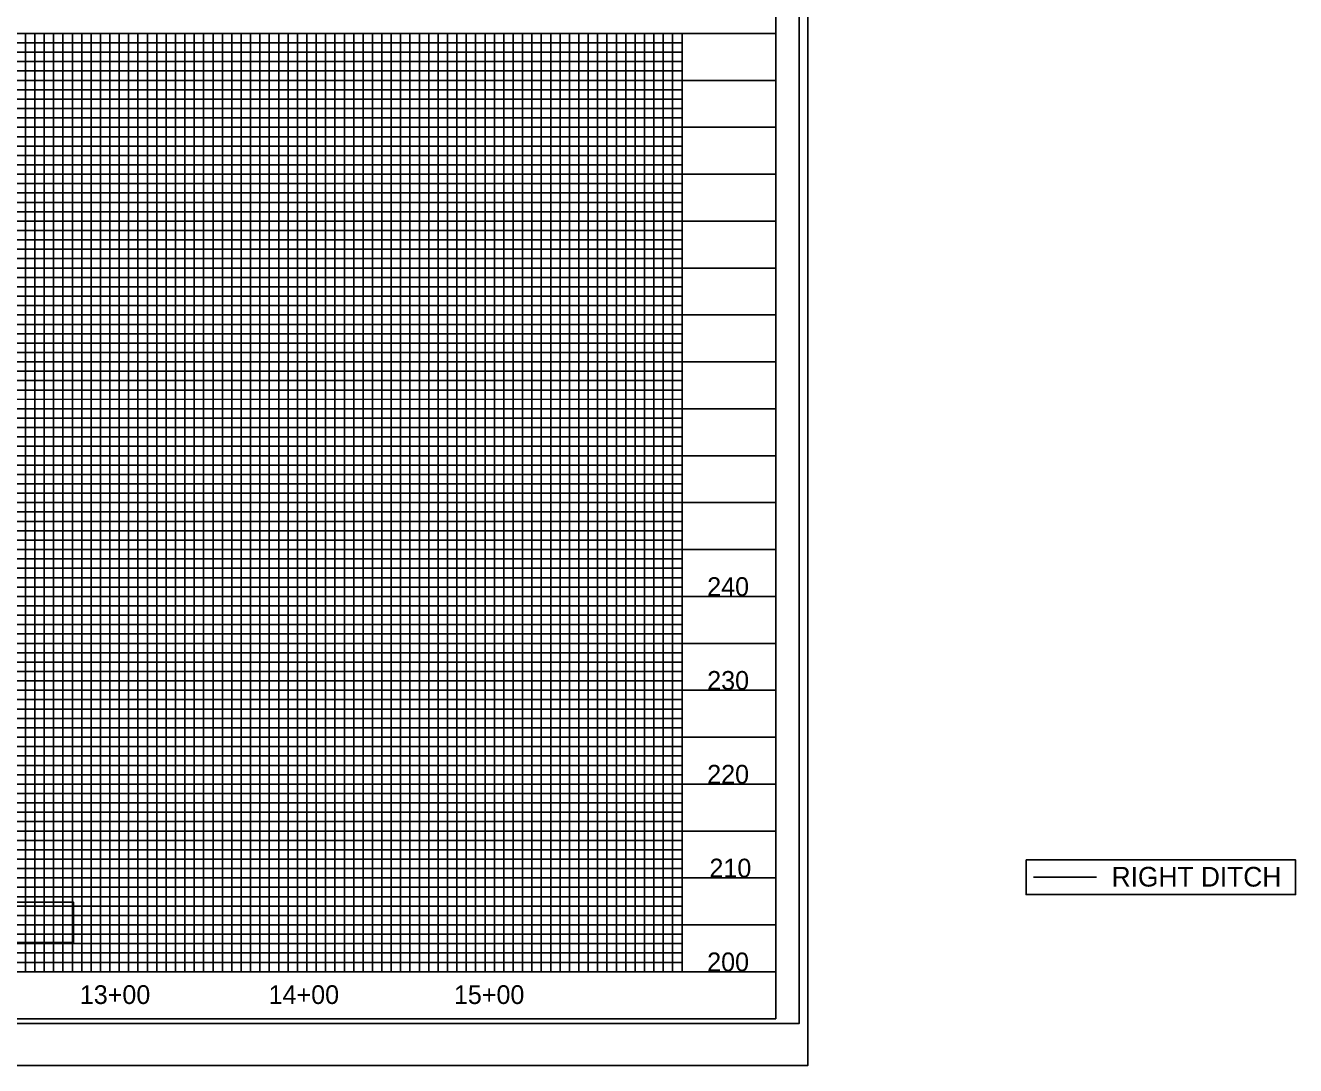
# Model space of a CAD drawing. Extents: x 1810963 to 1812908, y 722070 to 723170.
# Drawn here: x 1812230 to 1812908, y 722070 to 722624 of the extents above; entities that cross this region are included whole.
import ezdxf

# ---------------------------------------------------------------- set-up
doc = ezdxf.new("R2010")
doc.units = 0
for name, color, linetype in [('Exist Horizontal Alignment Tick Label', 7, 'Continuous'), ('Old_Level_11', 7, 'Continuous'), ('Old_Level_2', 7, 'Continuous'), ('Prop Conc 2ft 6in Curb and Gutter', 7, 'Continuous'), ('Prop PFL VPI Symbol CELL', 7, 'Continuous'), ('Prop RDY Traffic Signal CELL', 7, 'Continuous'), ('Prop Shade Heavy', 7, 'Continuous'), ('Prop Shade Light', 7, 'Continuous'), ('Prop Vertical Profile Ditch Grade Right', 7, 'Continuous'), ('Scratch_Level_0', 7, 'Continuous'), ('Sheet Block Title CELL', 7, 'Continuous'), ('Sheet North Arrow CELL', 7, 'Continuous'), ('Sheet Symbology CELL', 7, 'Continuous'), ('Sheet Title CELL', 7, 'Continuous')]:
    doc.layers.add(name, color=color, linetype=linetype)

msp = doc.modelspace()

# ---------------------------------------------------------------- linework, layer by layer
at = {"layer": 'Old_Level_11'}
msp.add_lwpolyline([(1810976.46, 722092.33), (1812642.96, 722092.33), (1812642.96, 723147.43), (1810976.46, 723147.43)], close=True, dxfattribs=at)
at = {"layer": 'Old_Level_2'}
for points in [[(1812763.88, 722179.51), (1812907.55, 722179.51), (1812907.55, 722161.02), (1812763.88, 722161.02)], [(1811986.45, 722156.96), (1812256.15, 722156.96), (1812256.15, 722135.44), (1811986.45, 722135.44)]]:
    msp.add_lwpolyline(points, close=True, dxfattribs=at)
at = {"layer": 'Prop Conc 2ft 6in Curb and Gutter'}
for p, q in [((1811130.46, 722619.88), (1812630.35, 722619.88)), ((1812230.46, 722619.88), (1812230.46, 722119.88)), ((1812280.46, 722619.88), (1812280.46, 722119.88)), ((1812330.46, 722619.88), (1812330.46, 722119.88)), ((1812380.46, 722619.88), (1812380.46, 722119.88)), ((1812430.46, 722619.88), (1812430.46, 722119.88)), ((1812480.46, 722619.88), (1812480.46, 722119.88)), ((1812530.46, 722619.88), (1812530.46, 722119.88)), ((1812580.46, 722619.88), (1812580.46, 722119.88)), ((1811130.46, 722569.88), (1812630.35, 722569.88)), ((1811130.46, 722519.88), (1812630.35, 722519.88)), ((1811130.46, 722469.88), (1812630.35, 722469.88)), ((1811130.46, 722419.88), (1812630.35, 722419.88)), ((1811130.46, 722369.88), (1812630.35, 722369.88)), ((1811130.46, 722319.88), (1812630.35, 722319.88)), ((1811130.46, 722269.88), (1812630.35, 722269.88)), ((1811130.46, 722219.88), (1812630.35, 722219.88)), ((1811130.46, 722169.88), (1812630.35, 722169.88))]:
    msp.add_line(p, q, dxfattribs=at)
at = {"layer": 'Prop PFL VPI Symbol CELL'}
msp.add_lwpolyline([(1811180.46, 722619.88), (1812580.46, 722619.88), (1812580.46, 722119.88), (1811180.46, 722119.88)], close=True, dxfattribs=at)
at = {"layer": 'Prop RDY Traffic Signal CELL'}
msp.add_line((1810963.46, 722069.88), (1812647.46, 722069.88), dxfattribs=at)
at = {"layer": 'Prop Shade Heavy'}
for p, q in [((1812230.46, 722619.88), (1812280.46, 722619.88)), ((1812330.46, 722619.88), (1812380.46, 722619.88)), ((1812430.46, 722619.88), (1812480.46, 722619.88)), ((1812530.46, 722619.88), (1812580.46, 722619.88)), ((1812530.46, 722119.88), (1812530.46, 722119.88))]:
    msp.add_line(p, q, dxfattribs=at)
for points in [[(1812180.46, 722119.88), (1812230.46, 722119.88), (1812230.46, 722619.88), (1812280.46, 722619.88), (1812280.46, 722119.88), (1812330.46, 722119.88), (1812330.46, 722619.88), (1812380.46, 722619.88), (1812380.46, 722119.88), (1812430.46, 722119.88), (1812430.46, 722619.88), (1812480.46, 722619.88), (1812480.46, 722119.88), (1812530.46, 722119.88), (1812530.46, 722119.88), (1812530.46, 722619.88), (1812580.46, 722619.88), (1812580.46, 722119.88)], [(1812630.46, 722569.88), (1811130.46, 722569.88)], [(1812630.46, 722519.88), (1811130.46, 722519.88), (1811130.46, 722469.88), (1812630.46, 722469.88)], [(1812630.46, 722419.88), (1811130.46, 722419.88), (1811130.46, 722369.88), (1812630.46, 722369.88)], [(1812630.46, 722319.88), (1811130.46, 722319.88), (1811130.46, 722269.88), (1812630.46, 722269.88)], [(1812630.46, 722219.88), (1811130.46, 722219.88), (1811130.46, 722219.88), (1811130.46, 722169.88), (1812630.46, 722169.88)], [(1812630.46, 722119.88), (1811130.46, 722119.88)]]:
    msp.add_lwpolyline(points, dxfattribs=at)
at = {"layer": 'Prop Shade Light'}
for points in [[(1812205.46, 722119.88), (1812255.46, 722119.88), (1812255.46, 722619.88), (1812305.46, 722619.88), (1812305.46, 722119.88), (1812355.46, 722119.88), (1812355.46, 722619.88), (1812405.46, 722619.88), (1812405.46, 722119.88), (1812455.46, 722119.88), (1812455.46, 722619.88), (1812505.46, 722619.88), (1812505.46, 722119.88), (1812555.46, 722119.88), (1812555.46, 722619.88)], [(1811130.46, 722594.88), (1812630.46, 722594.88)], [(1812630.46, 722544.88), (1811130.46, 722544.88), (1811130.46, 722494.88), (1812630.46, 722494.88)], [(1812630.46, 722444.88), (1811130.46, 722444.88), (1811130.46, 722394.88), (1812630.46, 722394.88)], [(1812630.46, 722344.88), (1811130.46, 722344.88), (1811130.46, 722294.88), (1812630.46, 722294.88)], [(1812630.46, 722244.88), (1811130.46, 722244.88), (1811130.46, 722194.88), (1812630.46, 722194.88)], [(1812630.46, 722144.88), (1811130.46, 722144.88)]]:
    msp.add_lwpolyline(points, dxfattribs=at)
at = {"layer": 'Prop Vertical Profile Ditch Grade Right'}
msp.add_line((1812767.79, 722170.2), (1812801.44, 722170.2), dxfattribs=at)
at = {"layer": 'Sheet North Arrow CELL'}
msp.add_lwpolyline([(1810963.46, 722069.88), (1812647.46, 722069.88), (1812647.46, 723169.88), (1810963.46, 723169.88)], close=True, dxfattribs=at)
at = {"layer": 'Sheet Symbology CELL'}
for p, q in [((1811130.46, 722619.88), (1812630.46, 722619.88)), ((1812630.46, 722119.88), (1811130.46, 722119.88)), ((1811130.46, 722094.88), (1812630.46, 722094.88))]:
    msp.add_line(p, q, dxfattribs=at)
msp.add_lwpolyline([(1812630.46, 723144.88), (1811130.46, 723144.88), (1811130.46, 722094.88), (1812630.46, 722094.88)], close=True, dxfattribs=at)
at = {"layer": 'Sheet Title CELL'}
for p, q in [((1811180.46, 722614.88), (1812580.46, 722614.88)), ((1812580.46, 722609.88), (1811180.46, 722609.88)), ((1811180.46, 722604.88), (1812580.46, 722604.88)), ((1812580.46, 722599.88), (1811180.46, 722599.88)), ((1811180.46, 722589.88), (1812580.46, 722589.88)), ((1812580.46, 722584.88), (1811180.46, 722584.88)), ((1811180.46, 722579.88), (1812580.46, 722579.88)), ((1812580.46, 722574.88), (1811180.46, 722574.88)), ((1811180.46, 722564.88), (1812580.46, 722564.88)), ((1812580.46, 722559.88), (1811180.46, 722559.88)), ((1811180.46, 722554.88), (1812580.46, 722554.88)), ((1812580.46, 722549.88), (1811180.46, 722549.88)), ((1811180.46, 722539.88), (1812580.46, 722539.88)), ((1812580.46, 722534.88), (1811180.46, 722534.88)), ((1811180.46, 722529.88), (1812580.46, 722529.88)), ((1812580.46, 722524.88), (1811180.46, 722524.88)), ((1811180.46, 722514.88), (1812580.46, 722514.88)), ((1812580.46, 722509.88), (1811180.46, 722509.88)), ((1811180.46, 722504.88), (1812580.46, 722504.88)), ((1812580.46, 722499.88), (1811180.46, 722499.88)), ((1811180.46, 722489.88), (1812580.46, 722489.88)), ((1812580.46, 722484.88), (1811180.46, 722484.88)), ((1811180.46, 722479.88), (1812580.46, 722479.88)), ((1812580.46, 722474.88), (1811180.46, 722474.88)), ((1811180.46, 722464.88), (1812580.46, 722464.88)), ((1812580.46, 722459.88), (1811180.46, 722459.88)), ((1811180.46, 722454.88), (1812580.46, 722454.88)), ((1812580.46, 722449.88), (1811180.46, 722449.88)), ((1811180.46, 722439.88), (1812580.46, 722439.88)), ((1812580.46, 722434.88), (1811180.46, 722434.88)), ((1811180.46, 722429.88), (1812580.46, 722429.88)), ((1812580.46, 722424.88), (1811180.46, 722425.03)), ((1811180.46, 722414.88), (1812580.46, 722414.88)), ((1812580.46, 722409.88), (1811180.46, 722409.88)), ((1811180.46, 722404.88), (1812580.46, 722404.88)), ((1812580.46, 722399.88), (1811180.46, 722399.88)), ((1811180.46, 722389.88), (1812580.46, 722389.88)), ((1812580.46, 722384.88), (1811180.46, 722384.88)), ((1811180.46, 722379.88), (1812580.46, 722379.88)), ((1812580.46, 722374.88), (1811180.46, 722374.88)), ((1811180.46, 722364.88), (1812580.46, 722364.88)), ((1812580.46, 722359.88), (1811180.46, 722359.88)), ((1811180.46, 722354.88), (1812580.46, 722354.88)), ((1812580.46, 722349.88), (1811180.46, 722349.88)), ((1811180.46, 722339.88), (1812580.46, 722339.88)), ((1812580.46, 722334.88), (1811180.46, 722334.88)), ((1811180.46, 722329.88), (1812580.46, 722329.88)), ((1812580.46, 722324.88), (1811180.46, 722324.88)), ((1811180.46, 722314.88), (1812580.46, 722314.88)), ((1812580.46, 722309.88), (1811180.46, 722309.88)), ((1811180.46, 722304.88), (1812580.46, 722304.88)), ((1812580.46, 722299.88), (1811180.46, 722299.88)), ((1811180.46, 722289.88), (1812580.46, 722289.88)), ((1812580.46, 722284.88), (1811180.46, 722284.88)), ((1811180.46, 722279.88), (1812580.46, 722279.88)), ((1812580.46, 722274.88), (1811180.46, 722274.88)), ((1811180.46, 722264.88), (1812580.46, 722264.88)), ((1812580.46, 722259.88), (1811180.46, 722259.88)), ((1811180.46, 722254.88), (1812580.46, 722254.88)), ((1812580.46, 722249.88), (1811180.46, 722249.88)), ((1811180.46, 722239.88), (1812580.46, 722239.88)), ((1812580.46, 722234.88), (1811180.46, 722234.88)), ((1811180.46, 722229.88), (1812580.46, 722229.88)), ((1812580.46, 722224.88), (1811180.46, 722224.88)), ((1811180.46, 722214.88), (1812580.46, 722214.88)), ((1812580.46, 722209.88), (1811180.46, 722209.88)), ((1811180.46, 722204.88), (1812580.46, 722204.88)), ((1812580.46, 722199.88), (1811180.46, 722199.88)), ((1811180.46, 722189.88), (1812580.46, 722189.88)), ((1812580.46, 722184.88), (1811180.46, 722184.88)), ((1811180.46, 722179.88), (1812580.46, 722179.88)), ((1812580.46, 722174.88), (1811180.46, 722174.88)), ((1811180.46, 722164.88), (1812580.46, 722164.88)), ((1812580.46, 722159.88), (1811180.46, 722159.88)), ((1811180.46, 722154.88), (1812580.46, 722154.88)), ((1812580.46, 722149.88), (1811180.46, 722149.88)), ((1811180.46, 722139.88), (1812580.46, 722139.88)), ((1812580.46, 722134.88), (1811180.46, 722134.88)), ((1811180.46, 722129.88), (1812580.46, 722129.88)), ((1811180.46, 722124.88), (1812580.46, 722124.88)), ((1812580.46, 722124.88), (1812580.46, 722124.88))]:
    msp.add_line(p, q, dxfattribs=at)
for points in [[(1812225.46, 722619.88), (1812235.46, 722619.88), (1812235.46, 722119.88), (1812240.46, 722119.88), (1812240.46, 722619.88), (1812245.46, 722619.88), (1812245.46, 722119.88), (1812250.46, 722119.88), (1812250.46, 722619.88), (1812260.46, 722619.88), (1812260.46, 722119.88), (1812265.46, 722119.88), (1812265.46, 722619.88), (1812270.46, 722619.88), (1812270.46, 722119.88), (1812275.46, 722119.88), (1812275.46, 722619.88), (1812285.46, 722619.88), (1812285.46, 722119.88), (1812290.46, 722119.88), (1812290.46, 722619.88), (1812295.46, 722619.88), (1812295.46, 722119.88), (1812300.46, 722119.88), (1812300.46, 722619.88), (1812310.46, 722619.88), (1812310.46, 722119.88), (1812315.46, 722119.88), (1812315.46, 722619.88), (1812320.46, 722619.88), (1812320.46, 722119.88)], [(1812320.46, 722119.88), (1812325.46, 722119.88), (1812325.46, 722619.88), (1812335.46, 722619.88), (1812335.46, 722119.88), (1812340.46, 722119.88), (1812340.46, 722619.88), (1812345.46, 722619.88), (1812345.46, 722119.88), (1812350.46, 722119.88), (1812350.46, 722619.88), (1812360.46, 722619.88), (1812360.46, 722119.88), (1812365.46, 722119.88), (1812365.46, 722619.88), (1812370.46, 722619.88), (1812370.46, 722119.88), (1812375.46, 722119.88), (1812375.46, 722619.88), (1812385.46, 722619.88), (1812385.46, 722119.88), (1812390.46, 722119.88), (1812390.46, 722619.88), (1812395.46, 722619.88), (1812395.46, 722119.88), (1812400.46, 722119.88), (1812400.46, 722619.88), (1812410.46, 722619.88), (1812410.46, 722119.88), (1812415.46, 722119.88), (1812415.46, 722619.88), (1812420.46, 722619.88), (1812420.46, 722119.88), (1812425.46, 722119.88), (1812425.46, 722619.88), (1812435.46, 722619.88), (1812435.46, 722119.88), (1812440.46, 722119.88), (1812440.46, 722619.88), (1812445.46, 722619.88), (1812445.46, 722119.88), (1812450.46, 722119.88), (1812450.46, 722619.88), (1812460.46, 722619.88), (1812460.46, 722119.88), (1812465.46, 722119.88), (1812465.46, 722619.88), (1812470.46, 722619.88), (1812470.46, 722119.88), (1812475.46, 722119.88), (1812475.46, 722619.88), (1812485.46, 722619.88), (1812485.46, 722119.88), (1812490.46, 722119.88), (1812490.46, 722619.88), (1812495.46, 722619.88), (1812495.46, 722119.88), (1812500.46, 722119.88), (1812500.46, 722619.88), (1812510.46, 722619.88), (1812510.46, 722119.88), (1812515.46, 722119.88), (1812515.46, 722619.88), (1812520.46, 722619.88), (1812520.46, 722119.88), (1812525.46, 722119.88), (1812525.46, 722619.88), (1812535.46, 722619.88), (1812535.46, 722119.88), (1812540.46, 722119.88), (1812540.46, 722619.88), (1812545.46, 722619.88), (1812545.46, 722119.88), (1812550.46, 722119.88), (1812550.46, 722619.88), (1812560.46, 722619.88), (1812560.46, 722119.88), (1812565.46, 722119.88), (1812565.46, 722619.88), (1812570.46, 722619.88), (1812570.46, 722119.88), (1812575.46, 722119.88), (1812575.46, 722619.88), (1812580.46, 722619.88)]]:
    msp.add_lwpolyline(points, dxfattribs=at)

# ---------------------------------------------------------------- texts
at = {"layer": 'Exist Horizontal Alignment Tick Label'}
msp.add_text('RIGHT DITCH', height=10.5, rotation=360, dxfattribs=at).set_placement((1812809.48, 722165.27))
at = {"layer": 'Scratch_Level_0'}
for s, p in [('240', (1812593.89, 722320.13)), ('230', (1812593.89, 722270.13)), ('220', (1812593.89, 722220.13)), ('210', (1812595.09, 722170.13)), ('200', (1812593.89, 722120.13))]:
    msp.add_text(s, height=10, dxfattribs=at).set_placement(p)
at = {"layer": 'Sheet Block Title CELL'}
for s, p in [('13+00', (1812259.46, 722102.7)), ('14+00', (1812360.1, 722102.7)), ('15+00', (1812458.88, 722102.7))]:
    msp.add_text(s, height=10, dxfattribs=at).set_placement(p)

doc.saveas('drawing.dxf')
